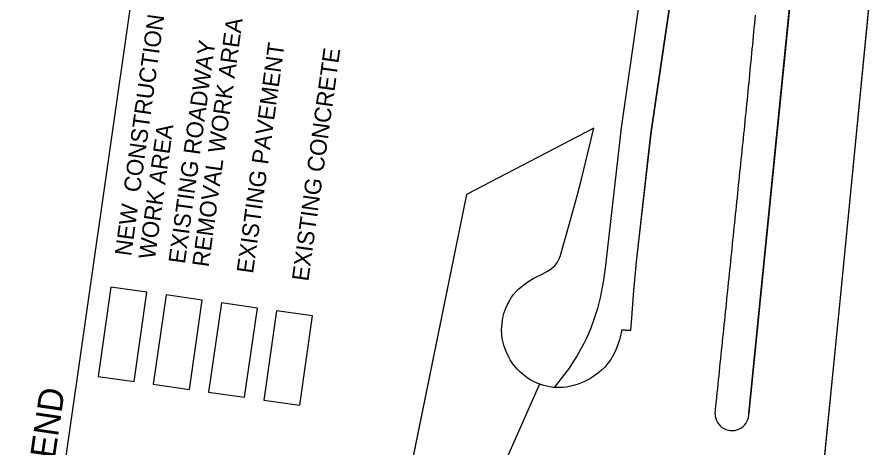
# Model space of a CAD drawing. Extents: x 1795987 to 1799689, y 243690 to 251545.
# Drawn here: x 1797501.1 to 1797904.5, y 249621.4 to 249823.3 of the extents above; entities that cross this region are included whole.
import ezdxf

# ---------------------------------------------------------------- set-up
doc = ezdxf.new("R2010")
doc.units = 0
for name, color, linetype in [('EP', 7, 'Continuous'), ('LEGEND', 7, 'Continuous'), ('Level 2', 7, 'Continuous'), ('Level 62', 7, 'Continuous'), ('Phase 2 Hatching', 7, 'Continuous'), ('SHADE_PRET', 7, 'Continuous')]:
    doc.layers.add(name, color=color, linetype=linetype)

msp = doc.modelspace()

# ---------------------------------------------------------------- linework, layer by layer
at = {"layer": 'EP'}
for p, q in [((1797886.98, 249691.77), (1797904.32, 249868.91)), ((1797784.12, 249770.06), (1797784.16, 249770.35)), ((1797798.04, 249768.52), (1797798.07, 249768.6)), ((1797873.14, 249551.66), (1797886.98, 249691.77)), ((1797784.55, 249676.63), (1797784.47, 249676.65)), ((1797745.91, 249651.24), (1797729.6, 249614.5)), ((1797745.93, 249651.27), (1797745.91, 249651.24))]:
    msp.add_line(p, q, dxfattribs=at)
for points in [[(1797870.9, 249904.98), (1797844.08, 249637.7)], [(1797870.9, 249904.98), (1797844.08, 249637.7)], [(1797808.71, 249840.51), (1797805.6, 249819.6), (1797798.07, 249768.6), (1797791.21, 249708.51), (1797789.76, 249693.22), (1797788.98, 249682.23), (1797788.51, 249676.41), (1797786.02, 249676.51), (1797784.55, 249676.63), (1797783.39, 249672.03), (1797782.72, 249669.89), (1797781.53, 249666.89), (1797780.11, 249664.12), (1797779.3, 249662.82), (1797777.5, 249660.38), (1797776.5, 249659.24), (1797774.86, 249657.62), (1797773.78, 249656.68), (1797771.47, 249654.94), (1797769.6, 249653.77), (1797766.64, 249652.24), (1797763.51, 249651.02), (1797761.9, 249650.54), (1797758.61, 249649.86), (1797756.96, 249649.67), (1797754.46, 249649.59), (1797752.26, 249649.73), (1797750.8, 249649.93), (1797747.93, 249650.57), (1797745.93, 249651.27)], [(1797784.16, 249770.35), (1797792.55, 249828.15)], [(1797828.25, 249637.24), (1797828.44, 249639.23), (1797828.65, 249641.22), (1797828.85, 249643.21), (1797829.06, 249645.19), (1797829.26, 249647.18), (1797829.47, 249649.17), (1797829.67, 249651.16), (1797829.88, 249653.15), (1797830.08, 249655.14), (1797830.28, 249657.13), (1797830.49, 249659.12), (1797830.69, 249661.11), (1797830.9, 249663.1), (1797831.1, 249665.09), (1797831.31, 249667.08), (1797831.51, 249669.07), (1797831.72, 249671.06), (1797831.92, 249673.05), (1797832.13, 249675.04), (1797832.33, 249677.03), (1797832.54, 249679.02), (1797832.74, 249681.01), (1797832.95, 249682.99), (1797833.15, 249684.98), (1797833.36, 249686.97), (1797833.56, 249688.96), (1797833.77, 249690.95), (1797833.97, 249692.94), (1797834.18, 249694.93), (1797834.38, 249696.92), (1797834.58, 249698.91), (1797834.79, 249700.9), (1797834.99, 249702.89), (1797835.2, 249704.88), (1797835.4, 249706.87), (1797835.61, 249708.86), (1797835.81, 249710.85), (1797836.02, 249712.84), (1797836.22, 249714.83), (1797836.43, 249716.82), (1797836.63, 249718.81), (1797836.84, 249720.8), (1797837.04, 249722.78), (1797837.25, 249724.77), (1797837.45, 249726.76), (1797837.66, 249728.75), (1797837.86, 249730.74), (1797838.07, 249732.73), (1797838.27, 249734.72), (1797838.48, 249736.71), (1797838.68, 249738.7), (1797838.88, 249740.69), (1797839.09, 249742.68), (1797839.29, 249744.67), (1797839.5, 249746.66), (1797839.7, 249748.65), (1797839.91, 249750.64), (1797840.11, 249752.63), (1797840.32, 249754.62), (1797840.52, 249756.61), (1797840.73, 249758.6), (1797840.93, 249760.59), (1797841.14, 249762.57), (1797841.34, 249764.56), (1797841.55, 249766.55), (1797841.75, 249768.54), (1797841.96, 249770.53), (1797842.16, 249772.52), (1797842.37, 249774.51), (1797842.57, 249776.5), (1797842.78, 249778.49), (1797842.98, 249780.48), (1797843.18, 249782.47), (1797843.39, 249784.46), (1797843.59, 249786.45), (1797843.79, 249788.44), (1797843.97, 249790.43), (1797844.16, 249792.42), (1797844.35, 249794.41), (1797844.54, 249796.4), (1797844.73, 249798.39), (1797844.92, 249800.39), (1797845.11, 249802.38), (1797845.3, 249804.37), (1797845.49, 249806.36), (1797845.68, 249808.35), (1797845.86, 249810.34), (1797846.05, 249812.33), (1797846.24, 249814.32), (1797846.43, 249816.31), (1797846.62, 249818.3), (1797846.81, 249820.3), (1797847, 249822.29), (1797847.19, 249824.28)], [(1797828.25, 249637.24), (1797828.44, 249639.23), (1797828.65, 249641.22), (1797828.85, 249643.21), (1797829.06, 249645.19), (1797829.26, 249647.18), (1797829.47, 249649.17), (1797829.67, 249651.16), (1797829.88, 249653.15), (1797830.08, 249655.14), (1797830.28, 249657.13), (1797830.49, 249659.12), (1797830.69, 249661.11), (1797830.9, 249663.1), (1797831.1, 249665.09), (1797831.31, 249667.08), (1797831.51, 249669.07), (1797831.72, 249671.06), (1797831.92, 249673.05), (1797832.13, 249675.04), (1797832.33, 249677.03), (1797832.54, 249679.02), (1797832.74, 249681.01), (1797832.95, 249682.99), (1797833.15, 249684.98), (1797833.36, 249686.97), (1797833.56, 249688.96), (1797833.77, 249690.95), (1797833.97, 249692.94), (1797834.18, 249694.93), (1797834.38, 249696.92), (1797834.58, 249698.91), (1797834.79, 249700.9), (1797834.99, 249702.89), (1797835.2, 249704.88), (1797835.4, 249706.87), (1797835.61, 249708.86), (1797835.81, 249710.85), (1797836.02, 249712.84), (1797836.22, 249714.83), (1797836.43, 249716.82), (1797836.63, 249718.81), (1797836.84, 249720.8), (1797837.04, 249722.78), (1797837.25, 249724.77), (1797837.45, 249726.76), (1797837.66, 249728.75), (1797837.86, 249730.74), (1797838.07, 249732.73), (1797838.27, 249734.72), (1797838.48, 249736.71), (1797838.68, 249738.7), (1797838.88, 249740.69), (1797839.09, 249742.68), (1797839.29, 249744.67), (1797839.5, 249746.66), (1797839.7, 249748.65), (1797839.91, 249750.64), (1797840.11, 249752.63), (1797840.32, 249754.62), (1797840.52, 249756.61), (1797840.73, 249758.6), (1797840.93, 249760.59), (1797841.14, 249762.57), (1797841.34, 249764.56), (1797841.55, 249766.55), (1797841.75, 249768.54), (1797841.96, 249770.53), (1797842.16, 249772.52), (1797842.37, 249774.51), (1797842.57, 249776.5), (1797842.78, 249778.49), (1797842.98, 249780.48), (1797843.18, 249782.47), (1797843.39, 249784.46), (1797843.59, 249786.45), (1797843.79, 249788.44), (1797843.97, 249790.43), (1797844.16, 249792.42), (1797844.35, 249794.41), (1797844.54, 249796.4), (1797844.73, 249798.39), (1797844.92, 249800.39), (1797845.11, 249802.38), (1797845.3, 249804.37), (1797845.49, 249806.36), (1797845.68, 249808.35), (1797845.86, 249810.34), (1797846.05, 249812.33), (1797846.24, 249814.32), (1797846.43, 249816.31), (1797846.62, 249818.3), (1797846.81, 249820.3), (1797847, 249822.29), (1797847.19, 249824.28)], [(1797745.62, 249651.38), (1797745.15, 249651.54), (1797743.36, 249652.35), (1797741.07, 249653.62), (1797739.98, 249654.34), (1797737.65, 249656.15), (1797736.56, 249657.14), (1797735.43, 249658.3), (1797733.39, 249660.81), (1797732.2, 249662.61), (1797731.49, 249663.86), (1797730.26, 249666.47), (1797729.19, 249669.53), (1797728.5, 249672.69), (1797728.29, 249674.3), (1797728.17, 249676.73), (1797728.2, 249678.21), (1797728.52, 249681.16), (1797728.91, 249683.1), (1797729.25, 249684.37), (1797730.11, 249686.86), (1797731.34, 249689.53), (1797732.86, 249692.03), (1797733.72, 249693.2), (1797735.13, 249694.84), (1797736.27, 249695.97), (1797738.75, 249698.01), (1797741.44, 249699.8), (1797743.31, 249700.88), (1797747.15, 249702.86), (1797749.73, 249704.17), (1797750.96, 249704.93), (1797752.4, 249706.07), (1797753.05, 249706.71), (1797753.91, 249707.77), (1797754.37, 249708.48), (1797755.14, 249709.99), (1797755.73, 249711.59), (1797756.67, 249714.92), (1797758.86, 249722.64), (1797763.53, 249739.46), (1797765.74, 249747.92), (1797767.68, 249755.71), (1797771.32, 249771.31), (1797711.7, 249740.2), (1797680.92, 249589.25)], [(1797784.12, 249770.06), (1797777.88, 249715.18), (1797776.82, 249706.8), (1797775.86, 249699.98), (1797775.3, 249696.62), (1797774.3, 249691.64), (1797773.08, 249686.72), (1797772.36, 249684.28), (1797771.62, 249682.02), (1797769.95, 249677.54), (1797768.04, 249673.15), (1797766.64, 249670.28), (1797763.57, 249664.69), (1797761.08, 249660.72), (1797759.76, 249658.78), (1797757.7, 249655.92), (1797752.74, 249649.7)]]:
    msp.add_lwpolyline(points, dxfattribs=at)
msp.add_arc((1797836.17, 249637.34), 7.92, 180.7407, 2.6438, dxfattribs=at)
msp.add_arc((1797836.17, 249637.34), 7.92, 180.7407, 2.6438, dxfattribs=at)
at = {"layer": 'LEGEND'}
msp.add_line((1797501.08, 249457.88), (1797556.62, 249845.43), dxfattribs=at)
for points in [[(1797555.87, 249652.47), (1797561.87, 249694.32), (1797544.97, 249696.74), (1797538.97, 249654.89)], [(1797581.77, 249648.76), (1797587.77, 249690.61), (1797570.87, 249693.03), (1797564.87, 249651.18)], [(1797607.67, 249645.05), (1797613.66, 249686.89), (1797596.77, 249689.32), (1797590.77, 249647.47)], [(1797633.57, 249641.34), (1797639.56, 249683.18), (1797622.67, 249685.6), (1797616.67, 249643.76)]]:
    msp.add_lwpolyline(points, close=True, dxfattribs=at)
at = {"layer": 'Level 2'}
msp.add_lwpolyline([(1797633.57, 249641.34), (1797639.56, 249683.18), (1797622.67, 249685.6), (1797616.67, 249643.76)], close=True, dxfattribs=at)
at = {"layer": 'Level 62'}
for p, q in [((1797886.98, 249691.77), (1797904.52, 249870.9)), ((1797771.32, 249771.31), (1797711.7, 249740.2)), ((1797711.7, 249740.2), (1797680.92, 249589.25)), ((1797850.8, 249325.49), (1797886.98, 249691.77))]:
    msp.add_line(p, q, dxfattribs=at)
for points in [[(1797870.9, 249904.98), (1797844.08, 249637.7)], [(1797873.14, 249551.66), (1797886.98, 249691.77), (1797904.32, 249868.91)], [(1797808.71, 249840.51), (1797805.6, 249819.6), (1797798.07, 249768.6), (1797791.21, 249708.51), (1797789.76, 249693.22), (1797788.98, 249682.23), (1797788.51, 249676.41), (1797786.02, 249676.51), (1797784.55, 249676.63), (1797783.39, 249672.03), (1797782.72, 249669.89), (1797781.53, 249666.89), (1797780.11, 249664.12), (1797779.3, 249662.82), (1797777.5, 249660.38), (1797776.5, 249659.24), (1797774.86, 249657.62), (1797773.78, 249656.68), (1797771.47, 249654.94), (1797769.6, 249653.77), (1797766.64, 249652.24), (1797763.51, 249651.02), (1797761.9, 249650.54), (1797758.61, 249649.86), (1797756.96, 249649.67), (1797754.46, 249649.59), (1797752.26, 249649.73), (1797750.8, 249649.93), (1797747.93, 249650.57), (1797745.15, 249651.54), (1797743.36, 249652.35), (1797741.07, 249653.62), (1797739.98, 249654.34), (1797737.65, 249656.15), (1797736.56, 249657.14), (1797735.43, 249658.3), (1797733.39, 249660.81), (1797732.2, 249662.61), (1797731.49, 249663.86), (1797730.26, 249666.47), (1797729.19, 249669.53), (1797728.5, 249672.69), (1797728.29, 249674.3), (1797728.17, 249676.73), (1797728.2, 249678.21), (1797728.52, 249681.16), (1797728.91, 249683.1), (1797729.25, 249684.37), (1797730.11, 249686.86), (1797731.34, 249689.53), (1797732.86, 249692.03), (1797733.72, 249693.2), (1797735.13, 249694.84), (1797736.27, 249695.97), (1797738.75, 249698.01), (1797741.44, 249699.8), (1797743.31, 249700.88), (1797747.15, 249702.86), (1797749.73, 249704.17), (1797750.96, 249704.93), (1797752.4, 249706.07), (1797753.05, 249706.71), (1797753.91, 249707.77), (1797754.37, 249708.48), (1797755.14, 249709.99), (1797755.73, 249711.59), (1797756.67, 249714.92), (1797758.86, 249722.64), (1797763.53, 249739.46), (1797765.74, 249747.92), (1797767.68, 249755.71), (1797771.32, 249771.31), (1797711.7, 249740.2), (1797680.92, 249589.25)], [(1797828.25, 249637.24), (1797828.44, 249639.23), (1797828.65, 249641.22), (1797828.85, 249643.21), (1797829.06, 249645.19), (1797829.26, 249647.18), (1797829.47, 249649.17), (1797829.67, 249651.16), (1797829.88, 249653.15), (1797830.08, 249655.14), (1797830.28, 249657.13), (1797830.49, 249659.12), (1797830.69, 249661.11), (1797830.9, 249663.1), (1797831.1, 249665.09), (1797831.31, 249667.08), (1797831.51, 249669.07), (1797831.72, 249671.06), (1797831.92, 249673.05), (1797832.13, 249675.04), (1797832.33, 249677.03), (1797832.54, 249679.02), (1797832.74, 249681.01), (1797832.95, 249682.99), (1797833.15, 249684.98), (1797833.36, 249686.97), (1797833.56, 249688.96), (1797833.77, 249690.95), (1797833.97, 249692.94), (1797834.18, 249694.93), (1797834.38, 249696.92), (1797834.58, 249698.91), (1797834.79, 249700.9), (1797834.99, 249702.89), (1797835.2, 249704.88), (1797835.4, 249706.87), (1797835.61, 249708.86), (1797835.81, 249710.85), (1797836.02, 249712.84), (1797836.22, 249714.83), (1797836.43, 249716.82), (1797836.63, 249718.81), (1797836.84, 249720.8), (1797837.04, 249722.78), (1797837.25, 249724.77), (1797837.45, 249726.76), (1797837.66, 249728.75), (1797837.86, 249730.74), (1797838.07, 249732.73), (1797838.27, 249734.72), (1797838.48, 249736.71), (1797838.68, 249738.7), (1797838.88, 249740.69), (1797839.09, 249742.68), (1797839.29, 249744.67), (1797839.5, 249746.66), (1797839.7, 249748.65), (1797839.91, 249750.64), (1797840.11, 249752.63), (1797840.32, 249754.62), (1797840.52, 249756.61), (1797840.73, 249758.6), (1797840.93, 249760.59), (1797841.14, 249762.57), (1797841.34, 249764.56), (1797841.55, 249766.55), (1797841.75, 249768.54), (1797841.96, 249770.53), (1797842.16, 249772.52), (1797842.37, 249774.51), (1797842.57, 249776.5), (1797842.78, 249778.49), (1797842.98, 249780.48), (1797843.18, 249782.47), (1797843.39, 249784.46), (1797843.59, 249786.45), (1797843.79, 249788.44), (1797843.97, 249790.43), (1797844.16, 249792.42), (1797844.35, 249794.41), (1797844.54, 249796.4), (1797844.73, 249798.39), (1797844.92, 249800.39), (1797845.11, 249802.38), (1797845.3, 249804.37), (1797845.49, 249806.36), (1797845.68, 249808.35), (1797845.86, 249810.34), (1797846.05, 249812.33), (1797846.24, 249814.32), (1797846.43, 249816.31), (1797846.62, 249818.3), (1797846.81, 249820.3), (1797847, 249822.29), (1797847.19, 249824.28)], [(1797590.77, 249647.47), (1797607.67, 249645.05), (1797613.66, 249686.89), (1797596.77, 249689.32), (1797590.77, 249647.47)]]:
    msp.add_lwpolyline(points, dxfattribs=at)
msp.add_arc((1797836.17, 249637.34), 7.92, 180.7407, 2.6438, dxfattribs=at)
at = {"layer": 'Phase 2 Hatching'}
msp.add_lwpolyline([(1797633.57, 249641.34), (1797639.56, 249683.18), (1797622.67, 249685.6), (1797616.67, 249643.76)], close=True, dxfattribs=at)
at = {"layer": 'SHADE_PRET'}
for p, q in [((1797844.08, 249637.7), (1797870.9, 249904.98)), ((1797786.02, 249676.51), (1797788.51, 249676.41))]:
    msp.add_line(p, q, dxfattribs=at)
for points in [[(1797798.07, 249768.6), (1797805.6, 249819.6), (1797808.71, 249840.51)], [(1797828.24, 249637.24), (1797828.44, 249639.23), (1797828.65, 249641.22), (1797828.85, 249643.21), (1797829.06, 249645.19), (1797829.26, 249647.18), (1797829.47, 249649.17), (1797829.67, 249651.16), (1797829.88, 249653.15), (1797830.08, 249655.14), (1797830.28, 249657.13), (1797830.49, 249659.12), (1797830.69, 249661.11), (1797830.9, 249663.1), (1797831.1, 249665.09), (1797831.31, 249667.08), (1797831.51, 249669.07), (1797831.72, 249671.06), (1797831.92, 249673.05), (1797832.13, 249675.04), (1797832.33, 249677.03), (1797832.54, 249679.02), (1797832.74, 249681.01), (1797832.95, 249682.99), (1797833.15, 249684.98), (1797833.36, 249686.97), (1797833.56, 249688.96), (1797833.77, 249690.95), (1797833.97, 249692.94), (1797834.18, 249694.93), (1797834.38, 249696.92), (1797834.58, 249698.91), (1797834.79, 249700.9), (1797834.99, 249702.89), (1797835.2, 249704.88), (1797835.4, 249706.87), (1797835.61, 249708.86), (1797835.81, 249710.85), (1797836.02, 249712.84), (1797836.22, 249714.83), (1797836.43, 249716.82), (1797836.63, 249718.81), (1797836.84, 249720.8), (1797837.04, 249722.78), (1797837.25, 249724.77), (1797837.45, 249726.76), (1797837.66, 249728.75), (1797837.86, 249730.74), (1797838.07, 249732.73), (1797838.27, 249734.72), (1797838.48, 249736.71), (1797838.68, 249738.7), (1797838.88, 249740.69), (1797839.09, 249742.68), (1797839.29, 249744.67), (1797839.5, 249746.66), (1797839.7, 249748.65), (1797839.91, 249750.64), (1797840.11, 249752.63), (1797840.32, 249754.62), (1797840.52, 249756.61), (1797840.73, 249758.6), (1797840.93, 249760.59), (1797841.14, 249762.57), (1797841.34, 249764.56), (1797841.55, 249766.55), (1797841.75, 249768.54), (1797841.96, 249770.53), (1797842.16, 249772.52), (1797842.37, 249774.51), (1797842.57, 249776.5), (1797842.78, 249778.49), (1797842.98, 249780.48), (1797843.18, 249782.47), (1797843.39, 249784.46), (1797843.59, 249786.45), (1797843.62, 249786.68), (1797843.79, 249788.44), (1797843.97, 249790.43), (1797844.16, 249792.42), (1797844.35, 249794.41), (1797844.54, 249796.4), (1797844.73, 249798.39), (1797844.92, 249800.39), (1797845.11, 249802.38), (1797845.3, 249804.37), (1797845.49, 249806.36), (1797845.68, 249808.35), (1797845.86, 249810.34), (1797846.05, 249812.33), (1797846.24, 249814.32), (1797846.43, 249816.31), (1797846.62, 249818.3), (1797846.81, 249820.3), (1797847, 249822.29), (1797847.19, 249824.28)], [(1797784.47, 249676.65), (1797783.39, 249672.03), (1797782.72, 249669.89), (1797781.53, 249666.89), (1797780.11, 249664.12), (1797779.3, 249662.82), (1797777.5, 249660.38), (1797776.5, 249659.24), (1797774.86, 249657.62), (1797773.78, 249656.68), (1797771.47, 249654.94), (1797769.6, 249653.77), (1797766.64, 249652.24), (1797763.51, 249651.02), (1797761.9, 249650.54), (1797758.61, 249649.86), (1797756.96, 249649.67), (1797754.46, 249649.59), (1797752.26, 249649.73), (1797750.8, 249649.93), (1797747.93, 249650.57), (1797745.15, 249651.54), (1797743.36, 249652.35), (1797741.07, 249653.62), (1797739.98, 249654.34), (1797737.65, 249656.15), (1797736.56, 249657.14), (1797735.43, 249658.3), (1797733.39, 249660.81), (1797732.2, 249662.61), (1797731.49, 249663.86), (1797730.26, 249666.47), (1797729.19, 249669.53), (1797728.5, 249672.69), (1797728.29, 249674.3), (1797728.17, 249676.73), (1797728.2, 249678.21), (1797728.52, 249681.16), (1797728.91, 249683.1), (1797729.25, 249684.37), (1797730.11, 249686.86), (1797731.34, 249689.53), (1797732.86, 249692.03), (1797733.72, 249693.2), (1797735.13, 249694.84), (1797736.27, 249695.97), (1797738.75, 249698.01), (1797741.44, 249699.8), (1797743.31, 249700.88), (1797747.15, 249702.86), (1797749.73, 249704.17), (1797750.96, 249704.93), (1797752.4, 249706.07), (1797753.05, 249706.71), (1797753.91, 249707.77), (1797754.37, 249708.48), (1797755.14, 249709.99), (1797755.73, 249711.59), (1797756.67, 249714.92), (1797758.86, 249722.64), (1797763.53, 249739.46), (1797765.74, 249747.92), (1797767.68, 249755.71), (1797771.32, 249771.31)], [(1797798.04, 249768.52), (1797791.21, 249708.51), (1797789.76, 249693.22), (1797788.98, 249682.23), (1797788.51, 249676.41)], [(1797784.47, 249676.65), (1797783.39, 249672.03), (1797782.72, 249669.89), (1797781.53, 249666.89), (1797780.11, 249664.12), (1797779.3, 249662.82), (1797777.5, 249660.38), (1797776.5, 249659.24), (1797774.86, 249657.62), (1797773.78, 249656.68), (1797771.47, 249654.94), (1797769.6, 249653.77), (1797766.64, 249652.24), (1797763.51, 249651.02), (1797761.9, 249650.54), (1797758.61, 249649.86), (1797756.96, 249649.67), (1797754.46, 249649.59), (1797752.74, 249649.7)], [(1797784.55, 249676.63), (1797786.02, 249676.51)]]:
    msp.add_lwpolyline(points, dxfattribs=at)
msp.add_arc((1797836.17, 249637.34), 7.92, 180.7407, 2.6438, dxfattribs=at)

# ---------------------------------------------------------------- texts
at = {"layer": 'LEGEND'}
for s, height, rotation, p in [('NEW  CONSTRUCTION', 7.7999, 82.1569, (1797554.51, 249710.98)), ('REMOVAL WORK AREA', 7.7999, 82.1569, (1797590.79, 249705.84)), ('EXISTING ROADWAY', 7.7999, 82.1569, (1797579.66, 249707.38)), ('EXISTING PAVEMENT', 7.7999, 82.1569, (1797611.62, 249702.81)), ('EXISTING CONCRETE', 7.7999, 82.1569, (1797637.53, 249699.18)), ('WORK AREA', 7.8, 82.1569, (1797565.64, 249709.45)), ('LEGEND', 11.7, 81.6779, (1797514.15, 249585.02))]:
    msp.add_text(s, height=height, rotation=rotation, dxfattribs=at).set_placement(p)

doc.saveas('drawing.dxf')
